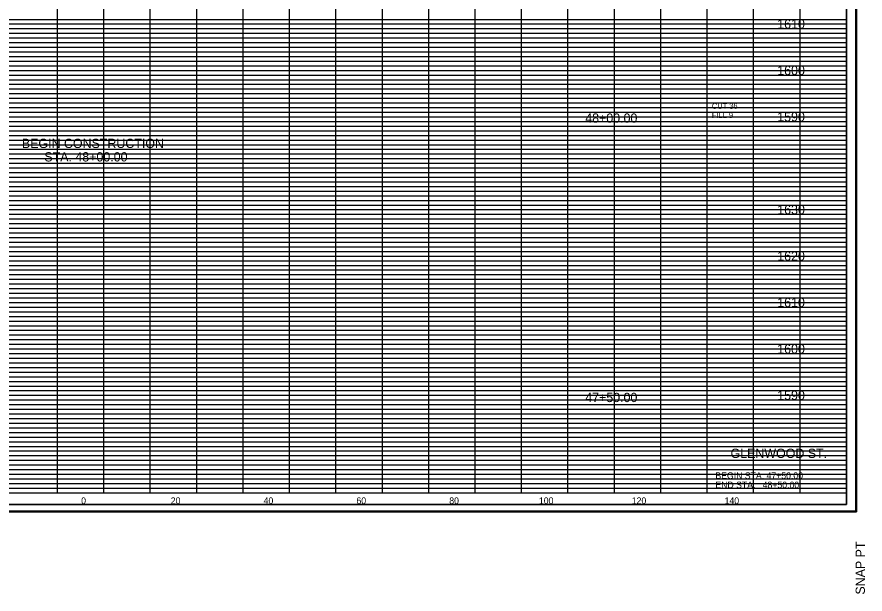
# Model space of a CAD drawing. Extents: x 980 to 1324, y 978 to 1497.
# Drawn here: x 1141.3 to 1324, y 978.2 to 1102.5 of the extents above; entities that cross this region are included whole.
import ezdxf

# ---------------------------------------------------------------- set-up
doc = ezdxf.new("R2010")
doc.units = 0
for name, color, linetype in [('DESIGN - SHEET - Corner Text', 7, 'Continuous'), ('DESIGN - SHEET - Light Grid', 7, 'Continuous'), ('DESIGN - SHEET - Linework', 7, 'Continuous'), ('DESIGN - SHEET - Plot Shape', 7, 'Continuous'), ('DESIGN - TYPICAL - Text', 7, 'Continuous')]:
    doc.layers.add(name, color=color, linetype=linetype)

# ---------------------------------------------------------------- blocks, each defined once
blk = doc.blocks.new('XSTSHT')
at = {"layer": 'DESIGN - SHEET - Light Grid'}
for p, q in [((8, 10.2), (16, 10.2)), ((8, 10.1), (16, 10.1)), ((16, 10.2), (24, 10.2)), ((16, 10.1), (24, 10.1)), ((24, 10.2), (32, 10.2)), ((24, 10.1), (32, 10.1)), ((8, 9.9), (16, 9.9)), ((16, 9.9), (24, 9.9)), ((24, 9.9), (32, 9.9)), ((8, 9.8), (16, 9.8)), ((8, 9.7), (16, 9.7)), ((16, 9.8), (24, 9.8)), ((16, 9.7), (24, 9.7)), ((24, 9.8), (32, 9.8)), ((24, 9.7), (32, 9.7)), ((8, 9.6), (16, 9.6)), ((16, 9.6), (24, 9.6)), ((24, 9.6), (32, 9.6)), ((8, 9.5), (16, 9.5)), ((8, 9.4), (16, 9.4)), ((16, 9.5), (24, 9.5)), ((16, 9.4), (24, 9.4)), ((24, 9.5), (32, 9.5)), ((24, 9.4), (32, 9.4)), ((8, 9.3), (16, 9.3)), ((8, 9.2), (16, 9.2)), ((16, 9.3), (24, 9.3)), ((16, 9.2), (24, 9.2)), ((24, 9.3), (32, 9.3)), ((24, 9.2), (32, 9.2)), ((8, 9.1), (16, 9.1)), ((16, 9.1), (24, 9.1)), ((24, 9.1), (32, 9.1)), ((8, 8.9), (16, 8.9)), ((8, 8.8), (16, 8.8)), ((16, 8.9), (24, 8.9)), ((16, 8.8), (24, 8.8)), ((24, 8.9), (32, 8.9)), ((24, 8.8), (32, 8.8)), ((8, 8.7), (16, 8.7)), ((8, 8.6), (16, 8.6)), ((16, 8.7), (24, 8.7)), ((16, 8.6), (24, 8.6)), ((24, 8.7), (32, 8.7)), ((24, 8.6), (32, 8.6)), ((8, 8.5), (16, 8.5)), ((16, 8.5), (24, 8.5)), ((24, 8.5), (32, 8.5)), ((8, 8.4), (16, 8.4)), ((8, 8.3), (16, 8.3)), ((16, 8.4), (24, 8.4)), ((16, 8.3), (24, 8.3)), ((24, 8.4), (32, 8.4)), ((24, 8.3), (32, 8.3)), ((8, 8.2), (16, 8.2)), ((8, 8.1), (16, 8.1)), ((16, 8.2), (24, 8.2)), ((16, 8.1), (24, 8.1)), ((24, 8.2), (32, 8.2)), ((24, 8.1), (32, 8.1)), ((8, 7.9), (16, 7.9)), ((16, 7.9), (24, 7.9)), ((24, 7.9), (32, 7.9)), ((8, 7.8), (16, 7.8)), ((8, 7.7), (16, 7.7)), ((16, 7.8), (24, 7.8)), ((16, 7.7), (24, 7.7)), ((24, 7.8), (32, 7.8)), ((24, 7.7), (32, 7.7)), ((8, 7.6), (16, 7.6)), ((8, 7.5), (16, 7.5)), ((16, 7.6), (24, 7.6)), ((16, 7.5), (24, 7.5)), ((24, 7.6), (32, 7.6)), ((24, 7.5), (32, 7.5)), ((8, 7.4), (16, 7.4)), ((16, 7.4), (24, 7.4)), ((24, 7.4), (32, 7.4)), ((8, 7.3), (16, 7.3)), ((8, 7.2), (16, 7.2)), ((16, 7.3), (24, 7.3)), ((16, 7.2), (24, 7.2)), ((24, 7.3), (32, 7.3)), ((24, 7.2), (32, 7.2)), ((8, 7.1), (16, 7.1)), ((16, 7.1), (24, 7.1)), ((24, 7.1), (32, 7.1)), ((8, 6.9), (16, 6.9)), ((8, 6.8), (16, 6.8)), ((16, 6.9), (24, 6.9)), ((16, 6.8), (24, 6.8)), ((24, 6.9), (32, 6.9)), ((24, 6.8), (32, 6.8)), ((8, 6.7), (16, 6.7)), ((8, 6.6), (16, 6.6)), ((16, 6.7), (24, 6.7)), ((16, 6.6), (24, 6.6)), ((24, 6.7), (32, 6.7)), ((24, 6.6), (32, 6.6)), ((8, 6.5), (16, 6.5)), ((8, 6.4), (16, 6.4)), ((16, 6.5), (24, 6.5)), ((16, 6.4), (24, 6.4)), ((24, 6.5), (32, 6.5)), ((24, 6.4), (32, 6.4)), ((8, 6.3), (16, 6.3)), ((16, 6.3), (24, 6.3)), ((24, 6.3), (32, 6.3)), ((8, 6.2), (16, 6.2)), ((8, 6.1), (16, 6.1)), ((16, 6.2), (24, 6.2)), ((16, 6.1), (24, 6.1)), ((24, 6.2), (32, 6.2)), ((24, 6.1), (32, 6.1)), ((8, 5.9), (16, 5.9)), ((16, 5.9), (24, 5.9)), ((24, 5.9), (32, 5.9)), ((8, 5.8), (16, 5.8)), ((8, 5.7), (16, 5.7)), ((16, 5.8), (24, 5.8)), ((16, 5.7), (24, 5.7)), ((24, 5.8), (32, 5.8)), ((24, 5.7), (32, 5.7)), ((8, 5.6), (16, 5.6)), ((8, 5.5), (16, 5.5)), ((16, 5.6), (24, 5.6)), ((16, 5.5), (24, 5.5)), ((24, 5.6), (32, 5.6)), ((24, 5.5), (32, 5.5)), ((8, 5.4), (16, 5.4)), ((8, 5.3), (16, 5.3)), ((16, 5.4), (24, 5.4)), ((16, 5.3), (24, 5.3)), ((24, 5.4), (32, 5.4)), ((24, 5.3), (32, 5.3)), ((8, 5.2), (16, 5.2)), ((16, 5.2), (24, 5.2)), ((24, 5.2), (32, 5.2)), ((8, 5.1), (16, 5.1)), ((16, 5.1), (24, 5.1)), ((24, 5.1), (32, 5.1)), ((8, 4.9), (16, 4.9)), ((8, 4.8), (16, 4.8)), ((16, 4.9), (24, 4.9)), ((16, 4.8), (24, 4.8)), ((24, 4.9), (32, 4.9)), ((24, 4.8), (32, 4.8)), ((8, 4.7), (16, 4.7)), ((8, 4.6), (16, 4.6)), ((16, 4.7), (24, 4.7)), ((16, 4.6), (24, 4.6)), ((24, 4.7), (32, 4.7)), ((24, 4.6), (32, 4.6)), ((8, 4.5), (16, 4.5)), ((8, 4.4), (16, 4.4)), ((16, 4.5), (24, 4.5)), ((16, 4.4), (24, 4.4)), ((24, 4.5), (32, 4.5)), ((24, 4.4), (32, 4.4)), ((8, 4.3), (16, 4.3)), ((16, 4.3), (24, 4.3)), ((24, 4.3), (32, 4.3)), ((8, 4.2), (16, 4.2)), ((8, 4.1), (16, 4.1)), ((16, 4.2), (24, 4.2)), ((16, 4.1), (24, 4.1)), ((24, 4.2), (32, 4.2)), ((24, 4.1), (32, 4.1)), ((8, 3.9), (16, 3.9)), ((16, 3.9), (24, 3.9)), ((24, 3.9), (32, 3.9)), ((8, 3.8), (16, 3.8)), ((8, 3.7), (16, 3.7)), ((16, 3.8), (24, 3.8)), ((16, 3.7), (24, 3.7)), ((24, 3.8), (32, 3.8)), ((24, 3.7), (32, 3.7)), ((8, 3.6), (16, 3.6)), ((8, 3.5), (16, 3.5)), ((16, 3.6), (24, 3.6)), ((16, 3.5), (24, 3.5)), ((24, 3.6), (32, 3.6)), ((24, 3.5), (32, 3.5)), ((8, 3.4), (16, 3.4)), ((8, 3.3), (16, 3.3)), ((16, 3.4), (24, 3.4)), ((16, 3.3), (24, 3.3)), ((24, 3.4), (32, 3.4)), ((24, 3.3), (32, 3.3)), ((8, 3.2), (16, 3.2)), ((16, 3.2), (24, 3.2)), ((24, 3.2), (32, 3.2)), ((8, 3.1), (16, 3.1)), ((16, 3.1), (24, 3.1)), ((24, 3.1), (32, 3.1)), ((8, 2.9), (16, 2.9)), ((8, 2.8), (16, 2.8)), ((16, 2.9), (24, 2.9)), ((16, 2.8), (24, 2.8)), ((24, 2.9), (32, 2.9)), ((24, 2.8), (32, 2.8)), ((8, 2.7), (16, 2.7)), ((8, 2.6), (16, 2.6)), ((16, 2.7), (24, 2.7)), ((16, 2.6), (24, 2.6)), ((24, 2.7), (32, 2.7)), ((24, 2.6), (32, 2.6)), ((8, 2.5), (16, 2.5)), ((8, 2.4), (16, 2.4)), ((16, 2.5), (24, 2.5)), ((16, 2.4), (24, 2.4)), ((24, 2.5), (32, 2.5)), ((24, 2.4), (32, 2.4)), ((8, 2.3), (16, 2.3)), ((8, 2.2), (16, 2.2)), ((16, 2.3), (24, 2.3)), ((16, 2.2), (24, 2.2)), ((24, 2.3), (32, 2.3)), ((24, 2.2), (32, 2.2)), ((8, 2.1), (16, 2.1)), ((16, 2.1), (24, 2.1)), ((24, 2.1), (32, 2.1)), ((8, 1.9), (16, 1.9)), ((16, 1.9), (24, 1.9)), ((24, 1.9), (32, 1.9)), ((8, 1.8), (16, 1.8)), ((8, 1.7), (16, 1.7)), ((16, 1.8), (24, 1.8)), ((16, 1.7), (24, 1.7)), ((24, 1.8), (32, 1.8)), ((24, 1.7), (32, 1.7)), ((8, 1.6), (16, 1.6)), ((8, 1.5), (16, 1.5)), ((16, 1.6), (24, 1.6)), ((16, 1.5), (24, 1.5)), ((24, 1.6), (32, 1.6)), ((24, 1.5), (32, 1.5)), ((8, 1.4), (16, 1.4)), ((8, 1.3), (16, 1.3)), ((16, 1.4), (24, 1.4)), ((16, 1.3), (24, 1.3)), ((24, 1.4), (32, 1.4)), ((24, 1.3), (32, 1.3)), ((8, 1.2), (16, 1.2)), ((8, 1.1), (16, 1.1)), ((16, 1.2), (24, 1.2)), ((16, 1.1), (24, 1.1)), ((24, 1.2), (32, 1.2)), ((24, 1.1), (32, 1.1)), ((8, 0.9), (16, 0.9)), ((8, 0.8), (16, 0.8)), ((16, 0.9), (24, 0.9)), ((16, 0.8), (24, 0.8)), ((24, 0.9), (32, 0.9)), ((24, 0.8), (32, 0.8)), ((8, 0.7), (16, 0.7)), ((8, 0.6), (16, 0.6)), ((16, 0.7), (24, 0.7)), ((16, 0.6), (24, 0.6)), ((24, 0.7), (32, 0.7)), ((24, 0.6), (32, 0.6)), ((8, 0.5), (16, 0.5)), ((8, 0.4), (16, 0.4)), ((16, 0.5), (24, 0.5)), ((16, 0.4), (24, 0.4)), ((24, 0.5), (32, 0.5)), ((24, 0.4), (32, 0.4)), ((8, 0.3), (16, 0.3)), ((8, 0.2), (16, 0.2)), ((16, 0.3), (24, 0.3)), ((16, 0.2), (24, 0.2)), ((24, 0.3), (32, 0.3)), ((24, 0.2), (32, 0.2)), ((8, 0.1), (16, 0.1)), ((16, 0.1), (24, 0.1)), ((24, 0.1), (32, 0.1))]:
    blk.add_line(p, q, dxfattribs=at)
at = {"layer": 'DESIGN - SHEET - Linework'}
for p, q in [((32.217, 21.414), (32.217, -0.414)), ((15, 0), (15, 21)), ((16, 0), (16, 21)), ((17, 0), (17, 21)), ((18, 0), (18, 21)), ((19, 0), (19, 21)), ((20, 0), (20, 21)), ((21, 0), (21, 21)), ((22, 0), (22, 21)), ((23, 0), (23, 21)), ((24, 0), (24, 21)), ((25, 0), (25, 21)), ((26, 0), (26, 21)), ((27, 0), (27, 21)), ((28, 0), (28, 20)), ((29, 0), (29, 20)), ((30, 0), (30, 20)), ((31, 0), (31, 20)), ((0, 10), (32, 10)), ((0, 9), (32, 9)), ((0, 8), (32, 8)), ((0, 7), (32, 7)), ((0, 6), (32, 6)), ((0, 5), (32, 5)), ((0, 4), (32, 4)), ((0, 3), (32, 3)), ((0, 2), (32, 2)), ((0, 1), (32, 1)), ((-1.823, -0.414), (32.217, -0.414))]:
    blk.add_line(p, q, dxfattribs=at)
blk.add_lwpolyline([(0, 21), (0, 0), (32, 0), (32, 21), (0, 21)], dxfattribs=at)
at = {"layer": 'DESIGN - SHEET - Plot Shape'}
for points in [[(-1.803, 21.394), (32.197, 21.394), (32.197, -0.394), (-1.803, -0.394)], [(-0.85, 21), (32, 21), (32, -0.25), (-0.85, -0.25)]]:
    blk.add_lwpolyline(points, close=True, dxfattribs=at)
at = {"layer": 'DESIGN - SHEET - Corner Text'}
blk.add_text('SNAP PT  ', height=0.2, rotation=90, dxfattribs=at).set_placement((32.397, -2.194))

msp = doc.modelspace()

# ---------------------------------------------------------------- linework, layer by layer
at = {"layer": 'DESIGN - SHEET - Plot Shape'}
msp.add_lwpolyline([(991.5, 997.5), (1320, 997.5), (1320, 1210), (991.5, 1210)], close=True, dxfattribs=at)

# ---------------------------------------------------------------- block references
at = {"layer": 'DESIGN - TYPICAL - Text', "xscale": 10, "yscale": 10}
msp.add_blockref('XSTSHT', (1000, 1000), dxfattribs=at)

# ---------------------------------------------------------------- texts
at = {"layer": 'DESIGN - SHEET - Corner Text'}
for s, height, p in [('GLENWOOD ST.', 2, (1295.02, 1007.5)), ('BEGIN STA. 47+50.00', 1.4, (1291.75, 1003)), ('END STA.   48+50.00', 1.4, (1291.75, 1001))]:
    msp.add_text(s, height=height, dxfattribs=at).set_placement(p)
at = {"layer": 'DESIGN - TYPICAL - Text'}
for s, height, p in [('     1610     ', 2, (1301.37, 1100)), ('     1600     ', 2, (1301.37, 1090)), ('CUT 36', 1.2, (1291, 1082.73)), ('     48+00.00     ', 2, (1260, 1079.73)), ('FILL 9', 1.2, (1291, 1080.73)), ('     1590     ', 2, (1301.37, 1080)), ('BEGIN CONSTRUCTION', 2, (1142.34, 1074.28)), ('STA. 48+00.00', 2, (1147.18, 1071.38)), ('     1630     ', 2, (1301.37, 1060)), ('     1620     ', 2, (1301.37, 1050)), ('     1610     ', 2, (1301.37, 1040)), ('     1600     ', 2, (1301.37, 1030)), ('     47+50.00     ', 2, (1260, 1019.54)), ('     1590     ', 2, (1301.37, 1020)), ('     0     ', 1.4, (1152.51, 997.6)), ('     0     ', 1.4, (1152.51, 997.6)), ('     20     ', 1.4, (1171.82, 997.6)), ('     40     ', 1.4, (1191.82, 997.6)), ('     60     ', 1.4, (1211.82, 997.6)), ('     80     ', 1.4, (1231.82, 997.6)), ('     100     ', 1.4, (1251.14, 997.6)), ('     120     ', 1.4, (1271.14, 997.6)), ('     140     ', 1.4, (1291.14, 997.6))]:
    msp.add_text(s, height=height, dxfattribs=at).set_placement(p)

doc.saveas('drawing.dxf')
